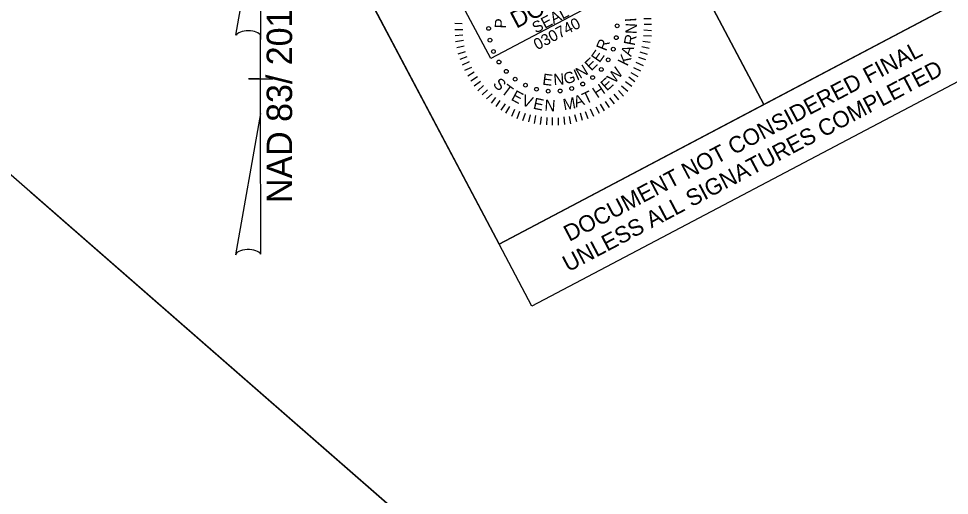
# Model space of a CAD drawing. Extents: x 1486990 to 1489232, y 497582 to 499336.
# Drawn here: x 1488267.7 to 1488578.8, y 498998.3 to 499157.9 of the extents above; entities that cross this region are included whole.
import ezdxf

# ---------------------------------------------------------------- set-up
doc = ezdxf.new("R2010")
doc.units = 0
for name, color, linetype in [('DTM Contours Minor', 7, 'Continuous'), ('PROF-MAJR', 7, 'Continuous'), ('Prop Drainage Structure Catch Basin Open Throat 1 CELL', 7, 'Continuous'), ('Prop Drainage Structure Drop Inlet Adjust CELL', 7, 'Continuous'), ('Prop Drainage Structure Pipe Outlet Channel Stabilization Detail CELL', 7, 'Continuous'), ('Prop Drainage Structure Plot Symbol 20 Scale', 7, 'Continuous'), ('Prop Horizontal Alignment Station Label', 7, 'Continuous')]:
    doc.layers.add(name, color=color, linetype=linetype)

msp = doc.modelspace()

# ---------------------------------------------------------------- linework, layer by layer
at = {"layer": 'DTM Contours Minor'}
for p, q in [((1488428.29, 499082.43), (1488605.18, 499175.83)), ((1488428.29, 499082.43), (1488605.18, 499175.83)), ((1488616.16, 499155.05), (1488439.27, 499061.65)), ((1488616.16, 499155.05), (1488439.27, 499061.65)), ((1488439.27, 499061.65), (1488428.29, 499082.43)), ((1488439.27, 499061.65), (1488428.29, 499082.43))]:
    msp.add_line(p, q, dxfattribs=at)
at = {"layer": 'PROF-MAJR'}
for p, q in [((1488479.18, 499157.81), (1488476.68, 499157.84)), ((1488413.46, 499156.35), (1488416.01, 499156.23)), ((1488479.27, 499155.93), (1488476.81, 499155.88)), ((1488413.46, 499154.2), (1488416.15, 499154.26)), ((1488413.6, 499152.24), (1488416.19, 499152.47)), ((1488479.23, 499151.95), (1488476.54, 499152.11)), ((1488479.27, 499153.78), (1488476.68, 499153.99)), ((1488413.78, 499150.18), (1488416.45, 499150.69)), ((1488414.13, 499148.22), (1488416.67, 499148.77)), ((1488478.42, 499147.9), (1488475.99, 499148.43)), ((1488478.82, 499149.93), (1488476.31, 499150.18)), ((1488414.67, 499146.13), (1488417.12, 499146.86)), ((1488415.29, 499144.31), (1488417.64, 499145.21)), ((1488477.93, 499145.84), (1488475.45, 499146.68)), ((1488416.1, 499142.36), (1488418.44, 499143.49)), ((1488476.63, 499142.09), (1488474.14, 499143.16)), ((1488477.3, 499144.03), (1488475.04, 499144.88)), ((1488416.9, 499140.64), (1488419.2, 499141.63)), ((1488417.88, 499138.78), (1488419.99, 499140.12)), ((1488474.83, 499138.43), (1488472.47, 499139.68)), ((1488475.64, 499140.33), (1488473.38, 499141.4)), ((1488418.9, 499137.06), (1488421.06, 499138.54)), ((1488420.01, 499135.38), (1488422.03, 499136.9)), ((1488472.62, 499135.12), (1488470.53, 499136.73)), ((1488473.7, 499136.71), (1488471.66, 499138.23)), ((1488421.21, 499133.75), (1488423.14, 499135.45)), ((1488422.63, 499132.35), (1488424.47, 499134)), ((1488424.13, 499131), (1488425.93, 499132.74)), ((1488469.87, 499131.97), (1488468.22, 499133.81)), ((1488471.31, 499133.52), (1488469.26, 499135.27)), ((1488425.77, 499129.6), (1488427.25, 499131.52)), ((1488427.27, 499128.47), (1488428.71, 499130.47)), ((1488465.21, 499128.15), (1488463.83, 499130.14)), ((1488466.93, 499129.4), (1488465.32, 499131.38)), ((1488468.38, 499130.73), (1488466.73, 499132.57)), ((1488428.96, 499127.21), (1488430.43, 499129.35)), ((1488430.59, 499126.27), (1488431.93, 499128.44)), ((1488432.58, 499125.28), (1488433.6, 499127.63)), ((1488434.39, 499124.43), (1488435.23, 499126.91)), ((1488458.05, 499124.37), (1488457.2, 499126.63)), ((1488460, 499125.17), (1488458.88, 499127.52)), ((1488461.91, 499126.07), (1488460.74, 499128.28)), ((1488463.54, 499127.04), (1488462.15, 499129.25)), ((1488436.19, 499123.8), (1488437.08, 499126.19)), ((1488438.26, 499123.31), (1488438.79, 499125.73)), ((1488440.1, 499122.81), (1488440.54, 499125.41)), ((1488442.13, 499122.41), (1488442.47, 499124.96)), ((1488444.23, 499122.28), (1488444.35, 499124.83)), ((1488446.2, 499122.18), (1488446.19, 499124.78)), ((1488448.21, 499122.23), (1488448.16, 499124.69)), ((1488450.27, 499122.41), (1488450.03, 499125)), ((1488452.27, 499122.68), (1488451.86, 499125.17)), ((1488454.32, 499123.3), (1488453.64, 499125.66)), ((1488456.23, 499123.75), (1488455.51, 499126.19))]:
    msp.add_line(p, q, dxfattribs=at)
for centre in [(1488424.81, 499154.6), (1488467.77, 499155.45), (1488467.49, 499151.5), (1488425.25, 499150.66), (1488466.48, 499147.66), (1488426.41, 499146.86), (1488428.25, 499143.35), (1488464.78, 499144.08), (1488430.7, 499140.23), (1488462.46, 499140.87), (1488433.68, 499137.62), (1488437.1, 499135.6), (1488456.25, 499135.98), (1488459.58, 499138.14), (1488440.82, 499134.24), (1488444.73, 499133.59), (1488448.7, 499133.67), (1488452.58, 499134.48)]:
    msp.add_circle(centre, 0.63, dxfattribs=at)
at = {"layer": 'Prop Drainage Structure Catch Basin Open Throat 1 CELL'}
msp.add_line((1488464.23, 499228.61), (1488516.75, 499129.17), dxfattribs=at)
for points in [[(1488464.23, 499228.61), (1488552.64, 499275.31), (1488605.19, 499175.82), (1488516.77, 499129.11)], [(1488375.76, 499181.89), (1488464.23, 499228.61), (1488516.77, 499129.11), (1488428.29, 499082.43)], [(1487698.94, 497679.61), (1487208.66, 498608.09), (1488358.21, 499215.12), (1488428.29, 499082.43), (1488605.19, 499175.82), (1489025.4, 498380.01)]]:
    msp.add_lwpolyline(points, close=True, dxfattribs=at)
at = {"layer": 'Prop Drainage Structure Drop Inlet Adjust CELL'}
msp.add_lwpolyline([(1488425.5, 499144.55), (1488414.53, 499165.33), (1488544.52, 499233.97), (1488555.49, 499213.19)], close=True, dxfattribs=at)
at = {"layer": 'Prop Drainage Structure Pipe Outlet Channel Stabilization Detail CELL'}
msp.add_line((1488271.73, 499099.83), (1488730.85, 498698.62), dxfattribs=at)
at = {"layer": 'Prop Drainage Structure Plot Symbol 20 Scale'}
msp.add_lwpolyline([(1487208.67, 498608.09), (1488222.08, 499143.23), (1488965.38, 498493.69), (1489025.4, 498380.01), (1487698.95, 497679.62)], close=True, dxfattribs=at)
at = {"layer": 'Prop Horizontal Alignment Station Label'}
for p, q in [((1488340.33, 499152.33), (1488348.53, 499198.68)), ((1488348.58, 499198.68), (1488348.58, 499150.88)), ((1488348.58, 499126.08), (1488348.58, 499152.28)), ((1488348.58, 499150.88), (1488348.58, 499152.23)), ((1488344.58, 499137.68), (1488344.53, 499137.68)), ((1488348.13, 499137.68), (1488344.58, 499137.68)), ((1488344.63, 499137.68), (1488352.63, 499137.68)), ((1488348.58, 499126.08), (1488340.23, 499078.83)), ((1488348.63, 499079.03), (1488348.58, 499126.08))]:
    msp.add_line(p, q, dxfattribs=at)
for centre, start_param, end_param in [((1488344.46, 499151.83), 0.216388, 2.908219), ((1488344.46, 499078.66), 0.201328, 3.141593)]:
    msp.add_ellipse(centre, major_axis=(4.23, -0.03), ratio=0.461098, start_param=start_param, end_param=end_param, dxfattribs=at)

# ---------------------------------------------------------------- texts
at = {"layer": 'DTM Contours Minor'}
for s, p in [('DOCUMENT NOT CONSIDERED FINAL', (1488451.76, 499083.12)), ('DOCUMENT NOT CONSIDERED FINAL', (1488451.76, 499083.12)), ('UNLESS ALL SIGNATURES COMPLETED', (1488451.38, 499072.97)), ('UNLESS ALL SIGNATURES COMPLETED', (1488451.38, 499072.97))]:
    msp.add_text(s, height=5.5, rotation=27.8351, dxfattribs=at).set_placement(p)
at = {"layer": 'PROF-MAJR'}
for s, height, rotation, p in [('SEAL', 3.759, 27.8351, (1488440.59, 499152.85)), ('P', 3.76, 87.9587, (1488430.59, 499154.54)), ('030740', 3.759, 27.8351, (1488441.06, 499147.26)), ('I', 3.78, 93.8815, (1488474.21, 499156.9)), ('N', 3.78, 87.2077, (1488474.28, 499152.64)), ('R', 3.78, 78.9854, (1488473.62, 499148.63)), ('R', 3.76, 68.1844, (1488464.09, 499146.78)), ('E', 3.76, 54.9919, (1488461.85, 499142.88)), ('K', 3.78, 63.9761, (1488471.16, 499141.74)), ('A', 3.78, 71.3568, (1488472.42, 499144.98)), ('N', 3.76, 30.9629, (1488455.34, 499137.64)), ('E', 3.76, 43.6408, (1488459.09, 499140.18)), ('E', 3.76, 352.7043, (1488442.63, 499135.79)), ('N', 3.76, 3.8935, (1488446.58, 499135.61)), ('G', 3.76, 15.3163, (1488450.42, 499135.83)), ('I', 3.76, 23.4597, (1488454.28, 499137.08)), ('W', 3.78, 49.8409, (1488466.93, 499135.93)), ('S', 3.78, 316.0471, (1488425.99, 499135.73)), ('T', 3.78, 323.4595, (1488428.68, 499133.18)), ('H', 3.78, 33.8463, (1488461.11, 499131.12)), ('E', 3.78, 41.9998, (1488464.32, 499133.47)), ('E', 3.78, 331.6576, (1488432.05, 499130.79)), ('T', 3.78, 25.2217, (1488457.21, 499129.18)), ('V', 3.78, 339.7649, (1488435.54, 499129.04)), ('E', 3.78, 348.0663, (1488439.48, 499127.76)), ('N', 3.78, 356.1641, (1488443.38, 499127.07)), ('M', 3.78, 10.1721, (1488450.01, 499127.18)), ('A', 3.78, 18.0173, (1488453.93, 499128.09))]:
    msp.add_text(s, height=height, rotation=rotation, dxfattribs=at).set_placement(p)
at = {"layer": 'Prop Drainage Structure Drop Inlet Adjust CELL'}
msp.add_text('DO NOT USE FOR R/W ACQUISITION', height=5.76, rotation=27.8351, dxfattribs=at).set_placement((1488434.07, 499154.45))
at = {"layer": 'Prop Horizontal Alignment Station Label'}
msp.add_text('NAD 83/ 2011', height=8.5, rotation=90, dxfattribs=at).set_placement((1488359.1, 499096.16))

doc.saveas('drawing.dxf')
